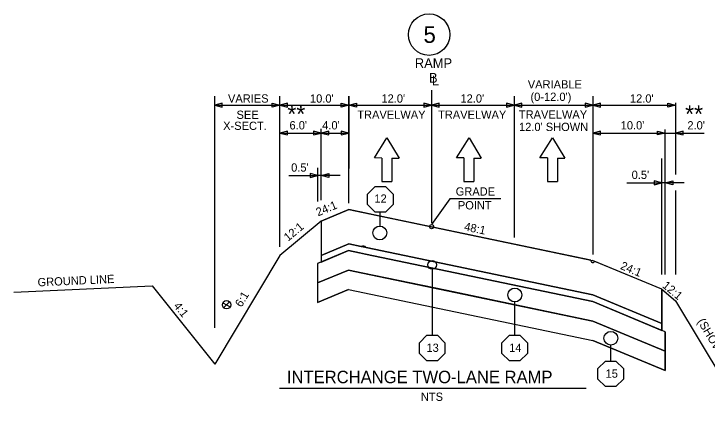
# Model space of a CAD drawing. Extents: x 4649 to 5578, y 4853 to 5383.
# Drawn here: x 5064.4 to 5164.9, y 5324.8 to 5383.2 of the extents above; entities that cross this region are included whole.
import ezdxf

# ---------------------------------------------------------------- set-up
doc = ezdxf.new("R2010")
doc.units = 0
for name, color, linetype in [('Level 2', 7, 'Continuous'), ('Level 25', 7, 'Continuous'), ('RD_QTY_Miscl_1', 7, 'Continuous'), ('RD_QTY_Miscl_2', 7, 'Continuous'), ('RD_QTY_Miscl_3', 7, 'Continuous'), ('RD_QTY_Miscl_4', 7, 'Continuous'), ('RD_SHT_Bndy', 7, 'Continuous'), ('RD_SHT_Typical', 7, 'Continuous'), ('RD_Sketch1', 7, 'Continuous'), ('RD_Sketch2', 7, 'Continuous'), ('RD_TX_TypSect', 7, 'Continuous')]:
    doc.layers.add(name, color=color, linetype=linetype)

msp = doc.modelspace()

# ---------------------------------------------------------------- linework, layer by layer
at = {"layer": 'Level 2'}
for p, q in [((5108.93, 5350.24), (5108.93, 5350.24)), ((5108.93, 5350.18), (5108.93, 5350.18))]:
    msp.add_line(p, q, dxfattribs=at)
at = {"layer": 'Level 25'}
for p, q in [((5127.63, 5356.42), (5124.96, 5352.72)), ((5135.02, 5356.42), (5127.63, 5356.42))]:
    msp.add_line(p, q, dxfattribs=at)
msp.add_circle((5124.6, 5380.22), 3, dxfattribs=at)
at = {"layer": 'RD_QTY_Miscl_1'}
for p, q in [((5112.95, 5354.9), (5108.95, 5353.23)), ((5108.93, 5353.21), (5108.93, 5348.25)), ((5108.93, 5348.25), (5112.95, 5349.93)), ((5112.95, 5349.93), (5114.77, 5349.55)), ((5115.48, 5349.4), (5148.34, 5342.56)), ((5158.34, 5343.34), (5148.61, 5347.39)), ((5158.34, 5338.39), (5158.34, 5343.34)), ((5148.34, 5342.56), (5158.34, 5338.39))]:
    msp.add_line(p, q, dxfattribs=at)
for points in [[(5148.05, 5347.58), (5117.52, 5353.94), (5112.95, 5354.9)], [(5108.95, 5353.23), (5108.94, 5353.21), (5108.93, 5353.21)]]:
    msp.add_lwpolyline(points, dxfattribs=at)
msp.add_circle((5117.45, 5351.5), 1, dxfattribs=at)
for centre, radius, start, end in [((5115.02, 5348.97), 0.63, 43.531, 112.936), ((5148.34, 5347.52), 0.3, 168.2335, 334.9679)]:
    msp.add_arc(centre, radius, start, end, dxfattribs=at)
at = {"layer": 'RD_QTY_Miscl_2'}
for p, q in [((5112.95, 5349.93), (5108.93, 5348.25)), ((5108.93, 5347.28), (5112.93, 5348.94)), ((5112.93, 5348.94), (5114.5, 5348.62)), ((5108.93, 5348.25), (5108.93, 5347.28)), ((5158.34, 5338.39), (5148.34, 5342.56)), ((5148.34, 5341.56), (5158.34, 5337.4)), ((5158.34, 5337.4), (5158.34, 5338.39))]:
    msp.add_line(p, q, dxfattribs=at)
for points in [[(5148.34, 5342.56), (5115.48, 5349.4), (5114.77, 5349.55), (5112.95, 5349.93)], [(5114.5, 5348.62), (5115.36, 5348.44), (5148.34, 5341.56)]]:
    msp.add_lwpolyline(points, dxfattribs=at)
at = {"layer": 'RD_QTY_Miscl_3'}
for p, q in [((5114.5, 5348.62), (5112.93, 5348.94)), ((5115.36, 5348.44), (5114.5, 5348.62)), ((5148.34, 5341.56), (5115.36, 5348.44)), ((5108.43, 5347.07), (5108.43, 5344.26)), ((5108.43, 5344.26), (5112.93, 5346.13)), ((5112.93, 5346.13), (5115, 5345.7)), ((5115, 5345.7), (5126.96, 5343.21)), ((5126.96, 5343.21), (5148.34, 5338.75)), ((5148.34, 5338.75), (5158.84, 5334.38)), ((5158.84, 5334.38), (5158.84, 5337.19))]:
    msp.add_line(p, q, dxfattribs=at)
for points in [[(5112.93, 5348.94), (5108.93, 5347.28), (5108.43, 5347.07)], [(5158.84, 5337.19), (5158.34, 5337.4), (5148.34, 5341.56)]]:
    msp.add_lwpolyline(points, dxfattribs=at)
at = {"layer": 'RD_QTY_Miscl_4'}
for p, q in [((5112.93, 5346.13), (5108.43, 5344.26)), ((5115, 5345.7), (5112.93, 5346.13)), ((5108.43, 5341.45), (5112.93, 5343.32)), ((5112.93, 5343.32), (5148.34, 5335.94)), ((5158.84, 5334.38), (5148.34, 5338.75)), ((5148.34, 5335.94), (5158.84, 5331.57)), ((5158.84, 5331.57), (5158.84, 5334.38))]:
    msp.add_line(p, q, dxfattribs=at)
for points in [[(5148.34, 5338.75), (5126.96, 5343.21), (5115, 5345.7)], [(5108.43, 5344.26), (5108.43, 5344.26), (5108.43, 5341.45)]]:
    msp.add_lwpolyline(points, dxfattribs=at)
at = {"layer": 'RD_SHT_Bndy'}
for p, q in [((5116.67, 5362.36), (5118.49, 5365.27)), ((5118.49, 5365.27), (5120.28, 5362.35)), ((5128.56, 5362.36), (5130.39, 5365.27)), ((5130.39, 5365.27), (5132.17, 5362.35)), ((5140.66, 5362.36), (5142.48, 5365.27)), ((5142.48, 5365.27), (5144.27, 5362.35)), ((5117.76, 5362.35), (5116.67, 5362.36)), ((5117.76, 5362.35), (5117.76, 5358.95)), ((5119.22, 5362.35), (5120.28, 5362.35)), ((5119.22, 5362.35), (5119.22, 5358.95)), ((5129.66, 5362.36), (5128.56, 5362.36)), ((5129.66, 5362.36), (5129.66, 5358.95)), ((5131.11, 5362.35), (5132.17, 5362.35)), ((5131.11, 5362.35), (5131.11, 5358.95)), ((5141.76, 5362.36), (5140.66, 5362.36)), ((5141.76, 5362.36), (5141.76, 5358.95)), ((5143.21, 5362.35), (5144.27, 5362.35)), ((5143.21, 5362.35), (5143.21, 5358.95)), ((5117.76, 5358.95), (5119.22, 5358.95)), ((5129.66, 5358.95), (5131.11, 5358.95)), ((5141.76, 5358.95), (5143.21, 5358.95))]:
    msp.add_line(p, q, dxfattribs=at)
at = {"layer": 'RD_SHT_Typical'}
for p, q in [((5108.95, 5353.23), (5112.95, 5354.9)), ((5108.95, 5353.23), (5102.96, 5348.23)), ((5108.93, 5353.22), (5108.93, 5347.28)), ((5108.93, 5348.25), (5112.95, 5349.93)), ((5112.93, 5348.94), (5108.43, 5347.07)), ((5112.93, 5348.94), (5148.34, 5341.56)), ((5102.96, 5348.23), (5093.51, 5332.49)), ((5108.43, 5347.07), (5108.43, 5341.45)), ((5158.34, 5343.34), (5148.28, 5347.53)), ((5112.93, 5346.13), (5108.43, 5344.26)), ((5112.93, 5346.13), (5148.34, 5338.75)), ((5084.43, 5343.85), (5093.51, 5332.49)), ((5112.93, 5343.32), (5108.43, 5341.45)), ((5112.93, 5343.32), (5148.34, 5335.94)), ((5158.34, 5343.34), (5160.34, 5341.68)), ((5158.34, 5343.34), (5158.34, 5337.4)), ((5158.34, 5338.39), (5148.34, 5342.56)), ((5160.34, 5341.68), (5170.44, 5324.84)), ((5158.84, 5337.19), (5148.34, 5341.56)), ((5158.84, 5334.38), (5148.34, 5338.75)), ((5158.84, 5337.19), (5158.84, 5331.57)), ((5158.84, 5331.57), (5148.34, 5335.94))]:
    msp.add_line(p, q, dxfattribs=at)
for points in [[(5112.95, 5354.9), (5148.28, 5347.53)], [(5112.95, 5349.93), (5148.34, 5342.56)]]:
    msp.add_lwpolyline(points, dxfattribs=at)
at = {"layer": 'RD_Sketch1'}
msp.add_line((5064.39, 5342.93), (5084.43, 5343.85), dxfattribs=at)
at = {"layer": 'RD_Sketch2'}
for points in [[(5119.37, 5357.13), (5119.37, 5355.6), (5118.29, 5354.52), (5116.76, 5354.52), (5115.68, 5355.6), (5115.68, 5357.13), (5116.76, 5358.21), (5118.29, 5358.21)], [(5126.89, 5335.6), (5126.89, 5334.07), (5125.81, 5332.99), (5124.28, 5332.99), (5123.2, 5334.07), (5123.2, 5335.6), (5124.28, 5336.68), (5125.81, 5336.68)], [(5138.85, 5335.6), (5138.85, 5334.07), (5137.77, 5332.99), (5136.24, 5332.99), (5135.16, 5334.07), (5135.16, 5335.6), (5136.24, 5336.68), (5137.77, 5336.68)], [(5152.78, 5331.87), (5152.78, 5330.34), (5151.7, 5329.26), (5150.17, 5329.26), (5149.09, 5330.34), (5149.09, 5331.87), (5150.17, 5332.95), (5151.7, 5332.95)]]:
    msp.add_lwpolyline(points, close=True, dxfattribs=at)
at = {"layer": 'RD_TX_TypSect'}
for p, q in [((5124.95, 5372.17), (5124.95, 5352.95)), ((5093.51, 5337.78), (5093.51, 5371.33)), ((5102.96, 5349.48), (5102.96, 5371.33)), ((5112.95, 5355.81), (5112.95, 5371.33)), ((5112.95, 5371.29), (5112.95, 5360.83)), ((5136.94, 5371.29), (5136.94, 5350.85)), ((5148.34, 5371.29), (5148.34, 5348.4)), ((5093.51, 5370), (5102.96, 5370)), ((5102.96, 5370), (5112.95, 5370)), ((5112.95, 5370), (5124.95, 5370)), ((5124.95, 5370), (5136.94, 5370)), ((5136.94, 5370), (5148.34, 5370)), ((5148.34, 5370), (5160.34, 5370)), ((5160.34, 5370.34), (5160.34, 5360.17)), ((5102.96, 5365.97), (5108.95, 5365.97)), ((5108.95, 5356.26), (5108.95, 5366.58)), ((5108.95, 5365.97), (5112.95, 5365.97)), ((5148.34, 5365.97), (5158.34, 5365.97)), ((5158.34, 5365.97), (5160.34, 5365.97)), ((5158.84, 5345.48), (5158.84, 5366.5)), ((5160.34, 5365.97), (5164.48, 5365.97)), ((5158.34, 5345.48), (5158.34, 5362.27)), ((5108.46, 5356.04), (5108.45, 5360.91)), ((5104.27, 5359.83), (5108.45, 5359.83)), ((5111.72, 5359.83), (5108.45, 5359.83)), ((5160.34, 5360.16), (5160.34, 5359.99)), ((5153.25, 5358.76), (5158.34, 5358.76)), ((5161.6, 5358.76), (5158.34, 5358.76)), ((5160.34, 5357.66), (5160.34, 5345.48)), ((5117.52, 5352.49), (5117.52, 5354.52)), ((5125.03, 5346.24), (5125.03, 5336.68)), ((5094.69, 5341.37), (5095.76, 5340.82)), ((5094.81, 5340.68), (5095.64, 5341.52)), ((5136.99, 5341.52), (5136.99, 5336.68)), ((5150.92, 5335.25), (5150.92, 5332.95)), ((5102.91, 5329.04), (5147.36, 5329.04))]:
    msp.add_line(p, q, dxfattribs=at)
for points in [[(5094.62, 5369.73), (5094.62, 5370.28), (5093.51, 5370)], [(5101.85, 5369.73), (5101.85, 5370.28), (5102.96, 5370)], [(5104.06, 5369.73), (5104.06, 5370.28), (5102.96, 5370)], [(5111.85, 5369.73), (5111.85, 5370.28), (5112.95, 5370)], [(5114.06, 5370.28), (5114.06, 5369.73), (5112.95, 5370)], [(5123.85, 5370.28), (5123.85, 5369.73), (5124.95, 5370)], [(5126.05, 5369.73), (5126.05, 5370.28), (5124.95, 5370)], [(5135.84, 5370.28), (5135.84, 5369.73), (5136.94, 5370)], [(5138.05, 5369.73), (5138.05, 5370.28), (5136.94, 5370)], [(5147.24, 5370.28), (5147.24, 5369.73), (5148.34, 5370)], [(5149.45, 5369.73), (5149.45, 5370.28), (5148.34, 5370)], [(5159.23, 5369.73), (5159.23, 5370.28), (5160.34, 5370)], [(5104.06, 5365.69), (5104.06, 5366.24), (5102.96, 5365.97)], [(5107.85, 5366.24), (5107.85, 5365.69), (5108.95, 5365.97)], [(5110.06, 5365.69), (5110.06, 5366.24), (5108.95, 5365.97)], [(5111.85, 5366.24), (5111.85, 5365.69), (5112.95, 5365.97)], [(5149.45, 5365.69), (5149.45, 5366.24), (5148.34, 5365.97)], [(5157.74, 5365.69), (5157.74, 5366.24), (5158.84, 5365.97)], [(5161.44, 5365.69), (5161.44, 5366.24), (5160.34, 5365.97)], [(5107.35, 5360.1), (5107.35, 5359.55), (5108.45, 5359.83)], [(5110.06, 5360.1), (5110.06, 5359.55), (5108.95, 5359.83)], [(5157.24, 5359.04), (5157.24, 5358.49), (5158.34, 5358.76)], [(5159.94, 5359.04), (5159.94, 5358.49), (5158.84, 5358.76)]]:
    msp.add_lwpolyline(points, close=True, dxfattribs=at)
for centre, radius in [((5124.96, 5352.42), 0.3), ((5117.45, 5351.5), 1), ((5125.05, 5346.87), 0.63), ((5137.03, 5342.52), 1), ((5095.23, 5341.1), 0.6), ((5150.96, 5336.25), 1)]:
    msp.add_circle(centre, radius, dxfattribs=at)

# ---------------------------------------------------------------- texts
at = {"layer": 'Level 25'}
msp.add_text('5', height=2.4, rotation=0.0016, dxfattribs=at).set_placement((5123.79, 5379.02))
at = {"layer": 'RD_TX_TypSect'}
for s, height, rotation, p in [('RAMP', 1.4, 0.0016, (5122.53, 5375.39)), ('B ', 1.4, 0.0016, (5124.58, 5373.26)), ('L', 1.4, 0.0016, (5124.99, 5372.87)), ('VARIABLE', 1.2, 0.0016, (5138.91, 5372.42)), ("(0-12.0')", 1.2, 0.0016, (5139.3, 5370.62)), ('VARIES', 1.2, 0.0016, (5095.44, 5370.37)), ("10.0'", 1.2, 0.0016, (5107.33, 5370.37)), ("12.0'", 1.2, 0.0016, (5117.69, 5370.37)), ("12.0'", 1.2, 0.0016, (5129.15, 5370.37)), ("12.0'", 1.2, 0.0016, (5153.72, 5370.37)), ('**', 2.5, 0.0016, (5104.05, 5367.48)), ('**', 2.5, 0.0016, (5161.72, 5367.48)), ('SEE', 1.2, 0.0016, (5096.68, 5368.02)), ('TRAVELWAY', 1.2, 0.0016, (5114.19, 5368.03)), ('TRAVELWAY', 1.2, 0.0016, (5125.9, 5368.03)), ('TRAVELWAY', 1.2, 0.0016, (5137.62, 5368.06)), ('X-SECT.', 1.2, 0.0016, (5094.74, 5366.42)), ("6.0'", 1.2, 0.0016, (5104.36, 5366.49)), ("4.0'", 1.2, 0.0016, (5109.1, 5366.49)), ("12.0' SHOWN", 1.2, 0.0016, (5137.64, 5366.26)), ("10.0'", 1.2, 0.0016, (5152.38, 5366.49)), ("2.0'", 1.2, 0.0016, (5162.05, 5366.49)), ("0.5'", 1.2, 0.0016, (5104.6, 5360.38)), ("0.5'", 1.2, 0.0016, (5153.97, 5359.32)), ('GRADE', 1.2, 0.0016, (5128.46, 5356.91)), ('12', 1.2, 0.0016, (5116.67, 5355.88)), ('24:1', 1.2, 22.6207, (5108.5, 5353.89)), ('POINT', 1.2, 0.0016, (5128.77, 5354.91)), ('12:1', 1.2, 39.8072, (5104.15, 5350.22)), ('48:1', 1.2, 348.2333, (5129.61, 5351.89)), ('24:1', 1.2, 337.3818, (5152.23, 5346.32)), ('GROUND LINE', 1.2, 2.6112, (5067.86, 5343.76)), ('12:1', 1.2, 320.1955, (5158.32, 5343.72)), ('6:1', 1.2, 59.0379, (5097.4, 5340.66)), ('4:1', 1.2, 308.6614, (5087.49, 5340.9)), ('(SHOWN 6:1)', 1.2, 300.9654, (5163.46, 5338.7)), ('13', 1.2, 0.0016, (5124.22, 5334.28)), ('14', 1.2, 0.0016, (5136.21, 5334.28)), ('15', 1.2, 0.0016, (5150.19, 5330.54)), ('INTERCHANGE TWO-LANE RAMP', 1.8, 0.0016, (5103.98, 5329.75)), ('NTS', 1.2, 0.0016, (5123.41, 5327.19))]:
    msp.add_text(s, height=height, rotation=rotation, dxfattribs=at).set_placement(p)

doc.saveas('drawing.dxf')
